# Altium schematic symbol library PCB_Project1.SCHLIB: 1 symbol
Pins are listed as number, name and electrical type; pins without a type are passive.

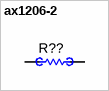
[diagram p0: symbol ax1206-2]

## ax1206-2
designator R??, comment ax1206-1  (value not drawn)
RES, 1.00k ohm, 1%, 0.25W, 1206+axial; Manufacturer: Vishay-Dale; CompType: Resistor; Res_ohm: 1000; Value_Code: 1k00; Tolerance_%: 1; Power_W: 0.25; VDC_V: 200; TempCo: 100 ppm/C; EIA_Code: E96; U/M: EA
signal-integrity model Resistor
simulation model Resistor
footprint ax1206 (1206 from SM-752 data)
pins: 1, 2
